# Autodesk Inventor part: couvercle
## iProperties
Created: 2011-01
Part Number: couvercle
Document SubType Name: Modeling
Designer: eric
Density: 1 g/cm^3
Mass: 109.109 g
Surface Area: 896.05 cm^2
Volume: 109.109 cm^3
Author: eric
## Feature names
1. Base1
